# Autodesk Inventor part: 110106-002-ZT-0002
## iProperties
Created: 2011-01
Part Number: 110106-002-ZT-0002
Document SubType Name: Modeling
Designer: Schulung
Density: 1 g/cm^3
Author: Schulung
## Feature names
1. Sweep1
2. Mirror1
3. Coil1
4. Revolution2
5. Loft1
6. Loft2
